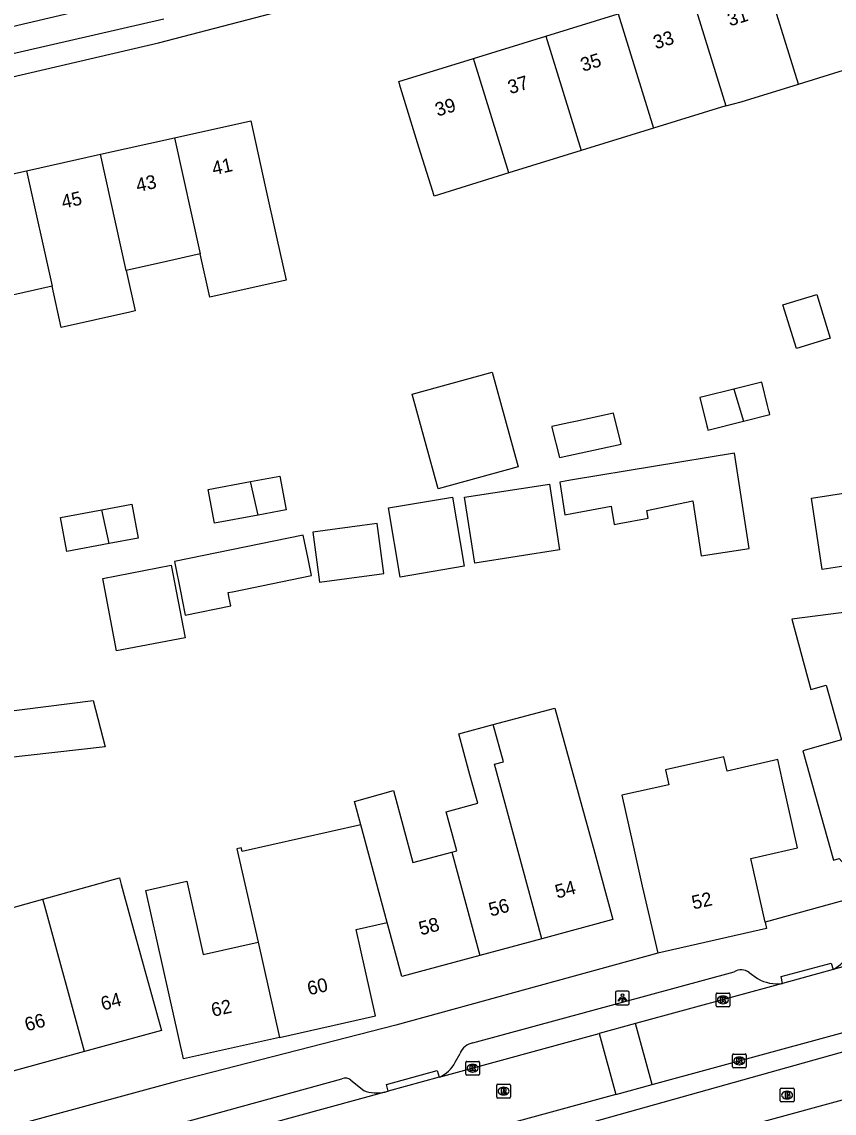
# Model space of a CAD drawing. Extents: x 163010 to 163853, y 382793 to 383982.
# Drawn here: x 163214.8 to 163274, y 383704.6 to 383784.1 of the extents above; entities that cross this region are included whole.
import ezdxf

# ---------------------------------------------------------------- set-up
doc = ezdxf.new("R2010")
doc.units = 0
for name, color, linetype in [('IMGEO_Brandkraan', 7, 'Continuous'), ('IMGEO_Kolk', 7, 'Continuous'), ('IMGEO_Lichtpunt', 7, 'Continuous'), ('IMGEO_Pand', 7, 'Continuous'), ('IMGEO_Pand_nummerreeks', 7, 'Continuous'), ('IMGEO_Rijbaan_lokaal_open', 7, 'Continuous'), ('IMGEO_Rioolput', 7, 'Continuous'), ('IMGEO_Voetpad_open', 7, 'Continuous')]:
    doc.layers.add(name, color=color, linetype=linetype)

msp = doc.modelspace()

# ---------------------------------------------------------------- linework, layer by layer
at = {"layer": 'IMGEO_Brandkraan'}
for p, q in [((163270.051, 383705.521), (163270.051, 383706.373)), ((163270.126, 383706.447), (163270.978, 383706.447)), ((163270.539, 383706.227), (163270.564, 383706.227)), ((163271.052, 383706.373), (163271.052, 383705.521)), ((163270.978, 383705.447), (163270.126, 383705.447)), ((163270.562, 383705.667), (163270.537, 383705.667))]:
    msp.add_line(p, q, dxfattribs=at)
for points in [[(163270.051, 383705.521), (163270.051, 383706.373)], [(163270.126, 383706.447), (163270.978, 383706.447)], [(163270.399, 383706.147), (163270.399, 383705.747), (163270.612, 383705.747)], [(163270.63, 383706.147), (163270.399, 383706.147)], [(163270.578, 383706.066), (163270.524, 383706.066), (163270.524, 383705.99)], [(163270.524, 383705.99), (163270.577, 383705.99)], [(163270.586, 383705.914), (163270.524, 383705.914), (163270.524, 383705.833)], [(163270.524, 383705.833), (163270.586, 383705.833)], [(163271.052, 383706.373), (163271.052, 383705.521)], [(163270.978, 383705.447), (163270.126, 383705.447)]]:
    msp.add_lwpolyline(points, dxfattribs=at)
for centre, radius, start, end in [((163270.128, 383706.371), 0.0765, 91.55205, 178.44795), ((163270.128, 383706.371), 0.0765, 91.55205, 178.44795), ((163270.579, 383706.028), 0.0379, 267.82845, 90.93552), ((163270.587, 383705.873), 0.0404, 269.87594, 90.50774), ((163270.634, 383706.002), 0.145, 59.4692, 91.53667), ((163270.659, 383706.049), 0.0922, 285.51372, 58.15012), ((163270.664, 383705.857), 0.105, 301.31148, 78.98903), ((163270.976, 383706.371), 0.0765, 1.55205, 88.44795), ((163270.976, 383706.371), 0.0765, 1.55205, 88.44795), ((163270.128, 383705.523), 0.0765, 181.55205, 268.44795), ((163270.128, 383705.523), 0.0765, 181.55205, 268.44795), ((163270.618, 383705.998), 0.251, 268.66757, 293.53466), ((163270.976, 383705.523), 0.0765, 271.55205, 358.44795), ((163270.976, 383705.523), 0.0765, 271.55205, 358.44795)]:
    msp.add_arc(centre, radius, start, end, dxfattribs=at)
for centre, major_axis, ratio, start_param, end_param in [((163270.538, 383705.947), (-0.387, 0.002), 0.722429, 4.712389, 7.853982), ((163270.563, 383705.947), (-0.39, 0.002), 0.717154, 1.570796, 4.712389)]:
    msp.add_ellipse(centre, major_axis=major_axis, ratio=ratio, start_param=start_param, end_param=end_param, dxfattribs=at)
at = {"layer": 'IMGEO_Kolk'}
for p, q in [((163265.374, 383712.451), (163265.374, 383713.303)), ((163265.449, 383713.377), (163266.301, 383713.377)), ((163265.862, 383713.157), (163265.887, 383713.157)), ((163266.375, 383713.303), (163266.375, 383712.451)), ((163266.301, 383712.377), (163265.449, 383712.377)), ((163265.885, 383712.597), (163265.86, 383712.597)), ((163247.136, 383707.474), (163247.136, 383708.326)), ((163247.211, 383708.4), (163248.063, 383708.4)), ((163248.137, 383708.326), (163248.137, 383707.474)), ((163266.567, 383708.01), (163266.567, 383708.862)), ((163266.642, 383708.936), (163267.494, 383708.936)), ((163267.055, 383708.716), (163267.08, 383708.716)), ((163267.568, 383708.862), (163267.568, 383708.01)), ((163247.647, 383707.62), (163247.622, 383707.62)), ((163247.624, 383708.18), (163247.649, 383708.18)), ((163267.494, 383707.936), (163266.642, 383707.936)), ((163267.078, 383708.156), (163267.053, 383708.156)), ((163248.063, 383707.4), (163247.211, 383707.4))]:
    msp.add_line(p, q, dxfattribs=at)
for points in [[(163265.374, 383712.451), (163265.374, 383713.303)], [(163265.449, 383713.377), (163266.301, 383713.377)], [(163265.695, 383713.077), (163265.818, 383713.077), (163265.818, 383712.926), (163265.948, 383713.077), (163266.112, 383713.077), (163265.966, 383712.926), (163266.119, 383712.677), (163265.967, 383712.677), (163265.882, 383712.841), (163265.818, 383712.774), (163265.818, 383712.677), (163265.695, 383712.677), (163265.695, 383713.077)], [(163266.375, 383713.303), (163266.375, 383712.451)], [(163266.301, 383712.377), (163265.449, 383712.377)], [(163247.136, 383707.474), (163247.136, 383708.326)], [(163247.211, 383708.4), (163248.063, 383708.4)], [(163248.137, 383708.326), (163248.137, 383707.474)], [(163266.567, 383708.01), (163266.567, 383708.862)], [(163266.642, 383708.936), (163267.494, 383708.936)], [(163266.888, 383708.636), (163267.011, 383708.636), (163267.011, 383708.485), (163267.141, 383708.636), (163267.305, 383708.636), (163267.159, 383708.485), (163267.312, 383708.236), (163267.16, 383708.236), (163267.075, 383708.4), (163267.011, 383708.333), (163267.011, 383708.236), (163266.888, 383708.236), (163266.888, 383708.636)], [(163267.568, 383708.862), (163267.568, 383708.01)], [(163247.457, 383708.1), (163247.58, 383708.1), (163247.58, 383707.949), (163247.71, 383708.1), (163247.874, 383708.1), (163247.728, 383707.949), (163247.881, 383707.7), (163247.729, 383707.7), (163247.644, 383707.864), (163247.58, 383707.797), (163247.58, 383707.7), (163247.457, 383707.7), (163247.457, 383708.1)], [(163267.494, 383707.936), (163266.642, 383707.936)], [(163248.063, 383707.4), (163247.211, 383707.4)]]:
    msp.add_lwpolyline(points, dxfattribs=at)
for centre, start, end in [((163265.451, 383713.301), 91.55205, 178.44795), ((163265.451, 383713.301), 91.55205, 178.44795), ((163266.299, 383713.301), 1.55205, 88.44795), ((163266.299, 383713.301), 1.55205, 88.44795), ((163265.451, 383712.453), 181.55205, 268.44795), ((163265.451, 383712.453), 181.55205, 268.44795), ((163266.299, 383712.453), 271.55205, 358.44795), ((163266.299, 383712.453), 271.55205, 358.44795), ((163247.213, 383708.324), 91.55205, 178.44795), ((163247.213, 383708.324), 91.55205, 178.44795), ((163248.061, 383708.324), 1.55205, 88.44795), ((163248.061, 383708.324), 1.55205, 88.44795), ((163266.644, 383708.86), 91.55205, 178.44795), ((163266.644, 383708.86), 91.55205, 178.44795), ((163267.492, 383708.86), 1.55205, 88.44795), ((163267.492, 383708.86), 1.55205, 88.44795), ((163247.213, 383707.476), 181.55205, 268.44795), ((163247.213, 383707.476), 181.55205, 268.44795), ((163248.061, 383707.476), 271.55205, 358.44795), ((163248.061, 383707.476), 271.55205, 358.44795), ((163266.644, 383708.012), 181.55205, 268.44795), ((163266.644, 383708.012), 181.55205, 268.44795), ((163267.492, 383708.012), 271.55205, 358.44795), ((163267.492, 383708.012), 271.55205, 358.44795)]:
    msp.add_arc(centre, 0.0765, start, end, dxfattribs=at)
for centre, major_axis, ratio, start_param, end_param in [((163265.861, 383712.877), (-0.387, 0.002), 0.722429, 4.712389, 7.853982), ((163265.886, 383712.877), (-0.39, 0.002), 0.717154, 1.570796, 4.712389), ((163267.054, 383708.436), (-0.387, 0.002), 0.722429, 4.712389, 7.853982), ((163267.079, 383708.436), (-0.39, 0.002), 0.717154, 1.570796, 4.712389), ((163247.623, 383707.9), (-0.387, 0.002), 0.722429, 4.712389, 7.853982), ((163247.648, 383707.9), (-0.39, 0.002), 0.717154, 1.570796, 4.712389)]:
    msp.add_ellipse(centre, major_axis=major_axis, ratio=ratio, start_param=start_param, end_param=end_param, dxfattribs=at)
at = {"layer": 'IMGEO_Lichtpunt'}
for p, q in [((163258.051, 383713.418), (163258.051, 383712.611)), ((163258.051, 383713.418), (163258.051, 383712.611)), ((163258.953, 383713.513), (163258.145, 383713.513)), ((163258.953, 383713.513), (163258.145, 383713.513)), ((163259.047, 383712.611), (163259.047, 383713.418)), ((163259.047, 383712.611), (163259.047, 383713.418)), ((163258.145, 383712.517), (163258.953, 383712.517)), ((163258.145, 383712.517), (163258.953, 383712.517))]:
    msp.add_line(p, q, dxfattribs=at)
for points in [[(163258.425, 383713.082), (163258.464, 383713.054), (163258.276, 383712.792), (163258.238, 383712.819), (163258.425, 383713.082)], [(163258.527, 383713.034), (163258.574, 383713.034), (163258.574, 383712.712), (163258.527, 383712.712), (163258.527, 383713.034)], [(163258.637, 383713.054), (163258.675, 383713.081), (163258.862, 383712.819), (163258.823, 383712.791), (163258.637, 383713.054)]]:
    msp.add_lwpolyline(points, dxfattribs=at)
msp.add_circle((163258.55, 383713.216), 0.0994, dxfattribs=at)
for centre, start, end in [((163258.145, 383713.418), 90, 180), ((163258.145, 383713.418), 90, 180), ((163258.953, 383713.418), 0, 90), ((163258.953, 383713.418), 0, 90), ((163258.145, 383712.611), 180, 270), ((163258.145, 383712.611), 180, 270), ((163258.953, 383712.611), 270, 0), ((163258.953, 383712.611), 270, 360)]:
    msp.add_arc(centre, 0.0946, start, end, dxfattribs=at)
at = {"layer": 'IMGEO_Pand'}
for points in [[(163271.372, 383779.557), (163268.79, 383787.928)], [(163263.518, 383786.3), (163266.089, 383777.966)], [(163252.972, 383783.045), (163258.245, 383784.673)], [(163258.245, 383784.673), (163260.817, 383776.339)], [(163247.699, 383781.418), (163252.972, 383783.045)], [(163252.972, 383783.045), (163255.544, 383774.712)], [(163250.27, 383773.084), (163244.833, 383771.406), (163244.734, 383771.723), (163243.735, 383774.962), (163242.393, 383779.31), (163242.26, 383779.739), (163247.699, 383781.418)], [(163250.27, 383773.084), (163247.699, 383781.418)], [(163271.372, 383779.557), (163276.14, 383781.029), (163276.645, 383781.185)], [(163266.089, 383777.966), (163267.205, 383778.271), (163271.372, 383779.557)], [(163266.089, 383777.966), (163260.817, 383776.339)], [(163225.919, 383775.638), (163231.476, 383776.871), (163232.559, 383771.99), (163233.35, 383768.421), (163234.048, 383765.273), (163228.492, 383764.041), (163227.793, 383767.188)], [(163260.817, 383776.339), (163255.544, 383774.712)], [(163220.532, 383774.444), (163225.919, 383775.638)], [(163225.919, 383775.638), (163227.793, 383767.188)], [(163215.145, 383773.249), (163220.532, 383774.444)], [(163222.406, 383765.994), (163220.532, 383774.444)], [(163255.544, 383774.712), (163250.27, 383773.084)], [(163209.758, 383772.054), (163215.145, 383773.249)], [(163215.145, 383773.249), (163217.012, 383764.832)], [(163227.793, 383767.188), (163225.348, 383766.646), (163222.406, 383765.994)], [(163222.406, 383765.994), (163223.062, 383763.037), (163222.676, 383762.951), (163217.675, 383761.842), (163217.012, 383764.832)], [(163217.012, 383764.832), (163211.625, 383763.637)], [(163270.242, 383763.478), (163272.71, 383764.237), (163273.69, 383761.052), (163271.222, 383760.292), (163270.242, 383763.478)], [(163245.125, 383750.09), (163243.237, 383756.97), (163249.072, 383758.571), (163250.96, 383751.691), (163245.125, 383750.09)], [(163267.383, 383755.012), (163269.294, 383755.487), (163269.262, 383755.615), (163269.226, 383755.76), (163269.131, 383756.142), (163268.707, 383757.85), (163266.664, 383757.342)], [(163266.664, 383757.342), (163264.518, 383756.808), (163264.184, 383756.725), (163264.693, 383754.677), (163264.739, 383754.492), (163264.771, 383754.363), (163267.383, 383755.012)], [(163266.664, 383757.342), (163267.383, 383755.012)], [(163253.404, 383754.613), (163253.422, 383754.542), (163253.963, 383752.362), (163254.08, 383752.387), (163258.464, 383753.342), (163257.905, 383755.593), (163255.136, 383754.99), (163254.645, 383754.883), (163253.404, 383754.613)], [(163254.928, 383750.738), (163254.508, 383750.668), (163253.989, 383750.582), (163254.356, 383748.201), (163254.874, 383748.297), (163257.741, 383748.828), (163257.947, 383747.493), (163258.306, 383747.56), (163260.428, 383747.953), (163260.338, 383748.517), (163263.678, 383749.219), (163264.293, 383745.21), (163267.773, 383745.744), (163266.706, 383752.69), (163254.928, 383750.738)], [(163232.011, 383748.169), (163228.849, 383747.576), (163228.386, 383750.045), (163231.467, 383750.623)], [(163231.467, 383750.623), (163233.587, 383751.02), (163234.05, 383748.551), (163232.011, 383748.169)], [(163232.011, 383748.169), (163231.467, 383750.623)], [(163247.794, 383744.674), (163247.051, 383749.473), (163253.237, 383750.432), (163253.981, 383745.633), (163247.794, 383744.674)], [(163272.316, 383749.408), (163275.141, 383749.841), (163275.937, 383744.657), (163273.112, 383744.223), (163272.316, 383749.408)], [(163220.621, 383748.563), (163222.813, 383748.974), (163223.276, 383746.505), (163221.165, 383746.109)], [(163241.52, 383748.704), (163246.182, 383749.489), (163247.03, 383744.446), (163242.369, 383743.662), (163241.52, 383748.704)], [(163221.165, 383746.109), (163218.075, 383745.53), (163217.612, 383747.999), (163220.621, 383748.563)], [(163221.165, 383746.109), (163220.621, 383748.563)], [(163239.605, 383747.417), (163235.997, 383746.924), (163236.495, 383743.28), (163240.832, 383743.873), (163241.181, 383743.921), (163240.683, 383747.564), (163240.334, 383747.516), (163239.605, 383747.417)], [(163226.38, 383742.519), (163226.487, 383741.993), (163226.711, 383740.896), (163230.024, 383741.572), (163229.91, 383742.13), (163229.827, 383742.53), (163230.154, 383742.597), (163235.901, 383743.77), (163235.653, 383744.987), (163235.303, 383746.701), (163225.917, 383744.784), (163226.38, 383742.519)], [(163225.691, 383744.52), (163226.7, 383739.237), (163221.708, 383738.284), (163220.699, 383743.567), (163225.691, 383744.52)], [(163274.351, 383723.176), (163275.057, 383722.338), (163277.188, 383722.936), (163277.516, 383724.065), (163279.727, 383724.686), (163278.374, 383729.5), (163277.551, 383732.426), (163277.508, 383732.58), (163276.157, 383737.385), (163276.347, 383737.438), (163276.906, 383737.595), (163276.865, 383737.877), (163276.799, 383738.332), (163276.369, 383741.299), (163270.901, 383740.585), (163272.281, 383735.487), (163273.399, 383735.802), (163274.522, 383731.806), (163271.696, 383731.012), (163272.578, 383727.872), (163273.931, 383723.058), (163274.351, 383723.176)], [(163213.086, 383733.804), (163219.992, 383734.676), (163220.879, 383731.298), (163213.535, 383730.473)], [(163249.136, 383732.915), (163253.62, 383734.126), (163255.802, 383726.281), (163256.539, 383723.553), (163257.843, 383718.725), (163252.674, 383717.329)], [(163246.126, 383723.641), (163246.479, 383723.736), (163245.714, 383726.567), (163248.011, 383727.188), (163247.57, 383728.821), (163247.377, 383729.534), (163246.645, 383732.242), (163249.136, 383732.915)], [(163252.674, 383717.329), (163249.24, 383730.037), (163249.887, 383730.212), (163249.136, 383732.915)], [(163268.944, 383718.534), (163267.9, 383723.165), (163271.315, 383723.936), (163270.215, 383728.814), (163269.865, 383730.368), (163266.177, 383729.537), (163265.942, 383730.578), (163261.697, 383729.621), (163261.939, 383728.546), (163258.506, 383727.772), (163259.308, 383724.216), (163259.998, 383721.157), (163261.121, 383716.284)], [(163239.503, 383725.621), (163239.041, 383727.329), (163241.882, 383728.113), (163243.296, 383722.877), (163246.126, 383723.641)], [(163239.503, 383725.621), (163230.846, 383723.685), (163230.789, 383723.939), (163230.477, 383723.869), (163232.019, 383717.083)], [(163241.423, 383718.512), (163239.503, 383725.621)], [(163246.126, 383723.641), (163248.162, 383716.11)], [(163216.339, 383720.204), (163221.915, 383721.763), (163222.052, 383721.267), (163222.757, 383718.711), (163223.653, 383715.461), (163224.971, 383710.637), (163219.369, 383709.107)], [(163233.575, 383710.144), (163226.582, 383708.577), (163225.489, 383713.456), (163223.833, 383720.844), (163226.816, 383721.512), (163228.01, 383716.185), (163232.019, 383717.083)], [(163211.704, 383715.584), (163213.104, 383715.966), (163212.394, 383718.567), (163212.258, 383719.063), (163212.499, 383719.131), (163216.339, 383720.204)], [(163219.369, 383709.107), (163216.475, 383719.708), (163216.339, 383720.204)], [(163233.575, 383710.144), (163240.57, 383711.711), (163239.477, 383716.591), (163239.16, 383718.005), (163241.423, 383718.512)], [(163248.162, 383716.11), (163242.486, 383714.577), (163241.423, 383718.512)], [(163268.944, 383718.534), (163269.048, 383718.072), (163261.121, 383716.284)], [(163232.019, 383717.083), (163233.575, 383710.144)], [(163252.674, 383717.329), (163248.162, 383716.11)], [(163219.369, 383709.107), (163213.883, 383707.609)]]:
    msp.add_lwpolyline(points, dxfattribs=at)
at = {"layer": 'IMGEO_Rijbaan_lokaal_open'}
for points in [[(163227.264, 383786.84), (163204.753, 383781.529), (163195.101, 383779.504), (163194.621, 383779.405)], [(163298.445, 383721.925), (163273.892, 383715.079)], [(163273.892, 383715.079), (163270.218, 383714.075)], [(163270.218, 383714.075), (163259.505, 383711.151)], [(163260.723, 383706.71), (163281.508, 383712.375)], [(163259.505, 383711.151), (163256.854, 383710.426)], [(163260.723, 383706.71), (163259.505, 383711.151)], [(163245.198, 383707.244), (163256.854, 383710.426)], [(163256.854, 383710.426), (163258.083, 383705.991)], [(163245.198, 383707.244), (163241.498, 383706.234)], [(163258.083, 383705.991), (163260.723, 383706.71)], [(163241.241, 383706.164), (163175.593, 383688.197)], [(163258.083, 383705.991), (163223.562, 383696.582)], [(163241.241, 383706.164), (163241.388, 383706.204), (163241.498, 383706.234)]]:
    msp.add_lwpolyline(points, dxfattribs=at)
at = {"layer": 'IMGEO_Rioolput'}
for p, q in [((163249.393, 383705.806), (163249.393, 383706.658)), ((163249.468, 383706.732), (163250.32, 383706.732)), ((163250.394, 383706.658), (163250.394, 383705.806)), ((163249.904, 383705.952), (163249.879, 383705.952)), ((163249.881, 383706.512), (163249.906, 383706.512)), ((163250.32, 383705.732), (163249.468, 383705.732))]:
    msp.add_line(p, q, dxfattribs=at)
for points in [[(163249.393, 383705.806), (163249.393, 383706.658)], [(163249.468, 383706.732), (163250.32, 383706.732)], [(163250.394, 383706.658), (163250.394, 383705.806)], [(163249.982, 383706.43), (163249.73, 383706.432), (163249.73, 383706.032)], [(163249.73, 383706.032), (163249.854, 383706.032), (163249.854, 383706.194), (163249.865, 383706.194)], [(163249.908, 383706.351), (163249.854, 383706.351), (163249.854, 383706.27)], [(163249.854, 383706.27), (163249.906, 383706.27)], [(163249.912, 383706.165), (163249.983, 383706.032), (163250.123, 383706.032), (163250.058, 383706.158)], [(163250.32, 383705.732), (163249.468, 383705.732)]]:
    msp.add_lwpolyline(points, dxfattribs=at)
for centre, radius, start, end in [((163249.47, 383706.656), 0.0765, 91.55205, 178.44795), ((163249.47, 383706.656), 0.0765, 91.55205, 178.44795), ((163250.318, 383706.656), 0.0765, 1.55205, 88.44795), ((163250.318, 383706.656), 0.0765, 1.55205, 88.44795), ((163249.864, 383706.141), 0.0533, 26.02933, 88.69889), ((163249.89, 383706.459), 0.19, 274.7715, 282.96867), ((163249.914, 383706.255), 0.0964, 77.00612, 93.18647), ((163249.928, 383706.312), 0.0378, 276.66336, 79.67722), ((163249.981, 383706.32), 0.109, 350.36119, 89.41601), ((163249.979, 383706.32), 0.112, 277.58423, 350.98172), ((163249.963, 383706.105), 0.108, 29.51342, 73.79051), ((163249.47, 383705.808), 0.0765, 181.55205, 268.44795), ((163249.47, 383705.808), 0.0765, 181.55205, 268.44795), ((163250.318, 383705.808), 0.0765, 271.55205, 358.44795), ((163250.318, 383705.808), 0.0765, 271.55205, 358.44795)]:
    msp.add_arc(centre, radius, start, end, dxfattribs=at)
for centre, major_axis, ratio, start_param, end_param in [((163249.88, 383706.232), (-0.387, 0.002), 0.722429, 4.712389, 7.853982), ((163249.905, 383706.232), (-0.39, 0.002), 0.717154, 1.570796, 4.712389)]:
    msp.add_ellipse(centre, major_axis=major_axis, ratio=ratio, start_param=start_param, end_param=end_param, dxfattribs=at)
at = {"layer": 'IMGEO_Voetpad_open'}
for points in [[(163119.034, 383764.505), (163142.448, 383767.592), (163175.747, 383772.352), (163205.449, 383778.073), (163224.77, 383782.549), (163248.813, 383788.839), (163265.635, 383793.903), (163278.283, 383798.072), (163287.084, 383801.323)], [(163225.148, 383784.285), (163205.13, 383779.692), (163197.682, 383778.077), (163197.349, 383778.052)], [(163282.25, 383722.208), (163268.944, 383718.534)], [(163250.659, 383699.08), (163310.588, 383715.439), (163310.002, 383718.169), (163310.732, 383720.107), (163312.031, 383720.54)], [(163261.121, 383716.284), (163242.045, 383711.035), (163225.973, 383706.902), (163169.191, 383691.469)], [(163270.218, 383714.075), (163270.126, 383714.569), (163273.755, 383715.561), (163273.892, 383715.079)], [(163247.661, 383709.738), (163266.699, 383714.928)], [(163267.778, 383714.865), (163268.394, 383714.425)], [(163280.627, 383711.519), (163280.11, 383710.623), (163230.834, 383696.804), (163226.808, 383695.816)], [(163246.375, 383708.338), (163246.724, 383708.974)], [(163241.498, 383706.234), (163241.367, 383706.716), (163245.056, 383707.723), (163245.198, 383707.244)], [(163170.273, 383688.608), (163191.332, 383694.26), (163238.122, 383707.13)], [(163238.781, 383707.029), (163239.711, 383706.271)]]:
    msp.add_lwpolyline(points, dxfattribs=at)
for centre, radius, start, end in [((163272.4, 383717.773), 3.079, 298.97632, 332.04101), ((163267.192, 383714.106), 0.959, 52.35849, 120.9584), ((163269.827, 383716.965), 2.916, 240.57082, 277.70473), ((163247.829, 383708.575), 1.175, 98.2314, 160.15402), ((163244.294, 383709.397), 2.335, 292.7775, 333.0363), ((163238.373, 383706.567), 0.617, 48.56737, 114.00564), ((163240.664, 383708.9), 2.796, 250.08336, 281.91575)]:
    msp.add_arc(centre, radius, start, end, dxfattribs=at)

# ---------------------------------------------------------------- texts
at = {"layer": 'IMGEO_Pand_nummerreeks'}
for s, rotation, p in [('31', 17.15436, (163266.38, 383783.75)), ('33', 17.15436, (163260.976, 383782.082)), ('35', 17.153, (163255.679, 383780.448)), ('37', 17.153, (163250.383, 383778.813)), ('39', 17.153, (163245.087, 383777.178)), ('41', 12.50618, (163228.775, 383772.913)), ('43', 12.50767, (163223.236, 383771.682)), ('45', 12.50767, (163217.807, 383770.478)), ('54', 15.11518, (163253.803, 383720.245)), ('56', 15.11463, (163248.963, 383718.937)), ('52', 12.7082, (163263.721, 383719.454)), ('58', 15.11518, (163243.872, 383717.562)), ('60', 12.62852, (163235.719, 383713.206)), ('64', 15.27505, (163220.71, 383712.086)), ('62', 12.62852, (163228.719, 383711.638)), ('66', 15.27505, (163215.166, 383710.571))]:
    msp.add_text(s, height=1, rotation=rotation, dxfattribs=at).set_placement(p)

doc.saveas('drawing.dxf')
